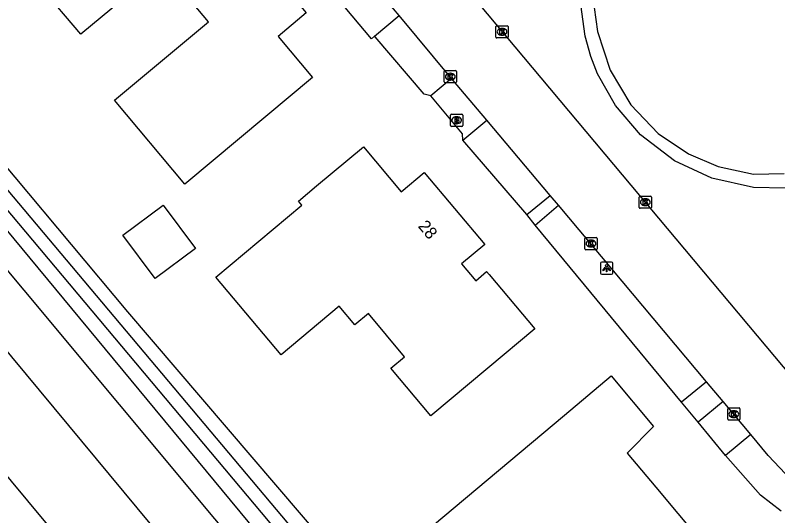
# Model space of a CAD drawing. Extents: x 157321 to 158827, y 386650 to 388532.
# Drawn here: x 158007.1 to 158069.6, y 386912.6 to 386953.6 of the extents above; entities that cross this region are included whole.
import ezdxf

# ---------------------------------------------------------------- set-up
doc = ezdxf.new("R2010")
doc.units = 0
for name, color, linetype in [('IMGEO_Brandkraan', 7, 'Continuous'), ('IMGEO_Groenvoorziening', 7, 'Continuous'), ('IMGEO_Kolk', 7, 'Continuous'), ('IMGEO_Lichtpunt', 7, 'Continuous'), ('IMGEO_Pand', 7, 'Continuous'), ('IMGEO_Pand_nummerreeks', 7, 'Continuous'), ('IMGEO_Rijbaan_lokaal_gesloten', 7, 'Continuous'), ('IMGEO_Voetpad_open', 7, 'Continuous'), ('IMGEO_Waterloop', 7, 'Continuous')]:
    doc.layers.add(name, color=color, linetype=linetype)

msp = doc.modelspace()

# ---------------------------------------------------------------- linework, layer by layer
at = {"layer": 'IMGEO_Brandkraan'}
for p, q in [((158042.816, 386944.616), (158042.816, 386945.468)), ((158042.891, 386945.542), (158043.743, 386945.542)), ((158043.817, 386945.468), (158043.817, 386944.616)), ((158043.304, 386945.322), (158043.329, 386945.322)), ((158043.743, 386944.542), (158042.891, 386944.542)), ((158043.327, 386944.762), (158043.302, 386944.762))]:
    msp.add_line(p, q, dxfattribs=at)
for points in [[(158042.816, 386944.616), (158042.816, 386945.468)], [(158042.891, 386945.542), (158043.743, 386945.542)], [(158043.817, 386945.468), (158043.817, 386944.616)], [(158043.164, 386945.242), (158043.164, 386944.842), (158043.377, 386944.842)], [(158043.395, 386945.242), (158043.164, 386945.242)], [(158043.343, 386945.161), (158043.289, 386945.161), (158043.289, 386945.085)], [(158043.289, 386945.085), (158043.342, 386945.085)], [(158043.351, 386945.009), (158043.289, 386945.009), (158043.289, 386944.928)], [(158043.289, 386944.928), (158043.351, 386944.928)], [(158043.743, 386944.542), (158042.891, 386944.542)]]:
    msp.add_lwpolyline(points, dxfattribs=at)
for centre, radius, start, end in [((158042.893, 386945.466), 0.0765, 91.55205, 178.44795), ((158042.893, 386945.466), 0.0765, 91.55205, 178.44795), ((158043.741, 386945.466), 0.0765, 1.55205, 88.44795), ((158043.741, 386945.466), 0.0765, 1.55205, 88.44795), ((158043.344, 386945.123), 0.0379, 267.82845, 90.93552), ((158043.352, 386944.968), 0.0404, 269.87594, 90.50774), ((158043.383, 386945.093), 0.251, 268.66757, 293.53466), ((158043.399, 386945.097), 0.145, 59.4692, 91.53667), ((158043.424, 386945.144), 0.0922, 285.51372, 58.15012), ((158043.429, 386944.952), 0.105, 301.31148, 78.98903), ((158042.893, 386944.618), 0.0765, 181.55205, 268.44795), ((158042.893, 386944.618), 0.0765, 181.55205, 268.44795), ((158043.741, 386944.618), 0.0765, 271.55205, 358.44795), ((158043.741, 386944.618), 0.0765, 271.55205, 358.44795)]:
    msp.add_arc(centre, radius, start, end, dxfattribs=at)
for centre, major_axis, ratio, start_param, end_param in [((158043.303, 386945.042), (-0.387, 0.002), 0.722429, 4.712389, 7.853982), ((158043.328, 386945.042), (-0.39, 0.002), 0.717154, 1.570796, 4.712389)]:
    msp.add_ellipse(centre, major_axis=major_axis, ratio=ratio, start_param=start_param, end_param=end_param, dxfattribs=at)
at = {"layer": 'IMGEO_Groenvoorziening'}
for points in [[(157915.669, 387039.524), (157916.246, 387034.499), (157917.326, 387029.652), (157918.224, 387026.707), (157925.534, 387014.398), (157933.739, 387003.394), (158036.298, 386879.994), (158040.875, 386875.274), (158045.999, 386870.991), (158051.541, 386867.268), (158057.356, 386864.191), (158059.718, 386863.157), (158065.313, 386860.377), (158069.288, 386859.404), (158071.922, 386859.047), (158074.577, 386858.967), (158077.228, 386859.164), (158080.09, 386859.682), (158109.645, 386869.131), (158107.666, 386875.322)], [(157937.472, 387021.971), (157943.823, 387013.736), (157955.389, 387000), (158000, 386947.022), (158042.278, 386896.814)], [(157938.087, 387014.677), (157950.334, 387000), (158000, 386940.482), (158039.093, 386893.634)], [(157939.879, 387006.192), (157945.025, 387000), (158000, 386933.844), (158041.131, 386884.348)], [(158070.263, 386939.479), (158067.652, 386939.528), (158064.236, 386940.299), (158061.179, 386941.73), (158058.402, 386943.856), (158056.356, 386946.242), (158054.878, 386948.842), (158054.312, 386950.281), (158053.85, 386951.938), (158053.495, 386954.52), (158053.571, 386957.187), (158055, 386966.678)], [(158056.05, 386965.433), (158055.065, 386959.117), (158054.575, 386955.997), (158054.591, 386954.286), (158054.858, 386952.32), (158055.896, 386949.14), (158057.604, 386946.303), (158059.842, 386943.968), (158062.335, 386942.282), (158064.755, 386941.25), (158067.645, 386940.623), (158070.176, 386940.675)], [(158041.197, 386947.04), (158040.654, 386947.173), (158036.643, 386951.87), (158036.592, 386951.93)], [(157997.832, 386951.408), (158016.34, 386929.351), (158048.856, 386891.347), (158052.006, 386888.362), (158054.735, 386886.23), (158061.143, 386882.788), (158063.836, 386881.61), (158066.74, 386880.636), (158072.605, 386879.295), (158075.571, 386878.874), (158081.422, 386878.627), (158087.103, 386878.964), (158090.042, 386879.509), (158092.91, 386880.238), (158101.35, 386883.538), (158104.009, 386884.795), (158111.36, 386888.673), (158097.876, 386904.822), (158091.265, 386912.857)], [(158049.074, 386937.309), (158043.836, 386943.4)], [(158061.764, 386921.937), (158049.754, 386936.46)], [(158065.373, 386917.573), (158063.11, 386920.309)]]:
    msp.add_lwpolyline(points, dxfattribs=at)
at = {"layer": 'IMGEO_Kolk'}
for p, q in [((158046.545, 386951.861), (158046.545, 386952.713)), ((158046.62, 386952.787), (158047.472, 386952.787)), ((158047.033, 386952.567), (158047.058, 386952.567)), ((158047.546, 386952.713), (158047.546, 386951.861)), ((158047.472, 386951.787), (158046.62, 386951.787)), ((158047.056, 386952.007), (158047.031, 386952.007)), ((158042.299, 386948.187), (158042.299, 386949.039)), ((158042.374, 386949.113), (158043.226, 386949.113)), ((158042.787, 386948.893), (158042.812, 386948.893)), ((158043.3, 386949.039), (158043.3, 386948.187)), ((158043.226, 386948.113), (158042.374, 386948.113)), ((158042.81, 386948.333), (158042.785, 386948.333)), ((158058.287, 386937.901), (158058.287, 386938.753)), ((158058.362, 386938.827), (158059.214, 386938.827)), ((158058.775, 386938.607), (158058.8, 386938.607)), ((158059.288, 386938.753), (158059.288, 386937.901)), ((158058.798, 386938.047), (158058.773, 386938.047)), ((158059.214, 386937.827), (158058.362, 386937.827)), ((158053.908, 386935.438), (158054.76, 386935.438)), ((158053.833, 386934.512), (158053.833, 386935.364)), ((158054.321, 386935.218), (158054.346, 386935.218)), ((158054.834, 386935.364), (158054.834, 386934.512)), ((158054.76, 386934.438), (158053.908, 386934.438)), ((158054.344, 386934.658), (158054.319, 386934.658)), ((158065.546, 386920.541), (158065.546, 386921.393)), ((158065.621, 386921.467), (158066.473, 386921.467)), ((158066.034, 386921.247), (158066.059, 386921.247)), ((158066.547, 386921.393), (158066.547, 386920.541)), ((158066.473, 386920.467), (158065.621, 386920.467)), ((158066.057, 386920.687), (158066.032, 386920.687))]:
    msp.add_line(p, q, dxfattribs=at)
for points in [[(158046.545, 386951.861), (158046.545, 386952.713)], [(158046.62, 386952.787), (158047.472, 386952.787)], [(158046.866, 386952.487), (158046.989, 386952.487), (158046.989, 386952.336), (158047.119, 386952.487), (158047.283, 386952.487), (158047.137, 386952.336), (158047.29, 386952.087), (158047.138, 386952.087), (158047.053, 386952.251), (158046.989, 386952.184), (158046.989, 386952.087), (158046.866, 386952.087), (158046.866, 386952.487)], [(158047.546, 386952.713), (158047.546, 386951.861)], [(158047.472, 386951.787), (158046.62, 386951.787)], [(158042.299, 386948.187), (158042.299, 386949.039)], [(158042.374, 386949.113), (158043.226, 386949.113)], [(158042.62, 386948.813), (158042.743, 386948.813), (158042.743, 386948.662), (158042.873, 386948.813), (158043.037, 386948.813), (158042.891, 386948.662), (158043.044, 386948.413), (158042.892, 386948.413), (158042.807, 386948.577), (158042.743, 386948.51), (158042.743, 386948.413), (158042.62, 386948.413), (158042.62, 386948.813)], [(158043.3, 386949.039), (158043.3, 386948.187)], [(158043.226, 386948.113), (158042.374, 386948.113)], [(158058.287, 386937.901), (158058.287, 386938.753)], [(158058.362, 386938.827), (158059.214, 386938.827)], [(158058.608, 386938.527), (158058.731, 386938.527), (158058.731, 386938.376), (158058.861, 386938.527), (158059.025, 386938.527), (158058.879, 386938.376), (158059.032, 386938.127), (158058.88, 386938.127), (158058.795, 386938.291), (158058.731, 386938.224), (158058.731, 386938.127), (158058.608, 386938.127), (158058.608, 386938.527)], [(158059.288, 386938.753), (158059.288, 386937.901)], [(158059.214, 386937.827), (158058.362, 386937.827)], [(158053.908, 386935.438), (158054.76, 386935.438)], [(158053.833, 386934.512), (158053.833, 386935.364)], [(158054.154, 386935.138), (158054.277, 386935.138), (158054.277, 386934.987), (158054.407, 386935.138), (158054.571, 386935.138), (158054.425, 386934.987), (158054.578, 386934.738), (158054.426, 386934.738), (158054.341, 386934.902), (158054.277, 386934.835), (158054.277, 386934.738), (158054.154, 386934.738), (158054.154, 386935.138)], [(158054.834, 386935.364), (158054.834, 386934.512)], [(158054.76, 386934.438), (158053.908, 386934.438)], [(158065.546, 386920.541), (158065.546, 386921.393)], [(158065.621, 386921.467), (158066.473, 386921.467)], [(158065.867, 386921.167), (158065.99, 386921.167), (158065.99, 386921.016), (158066.12, 386921.167), (158066.284, 386921.167), (158066.138, 386921.016), (158066.291, 386920.767), (158066.139, 386920.767), (158066.054, 386920.931), (158065.99, 386920.864), (158065.99, 386920.767), (158065.867, 386920.767), (158065.867, 386921.167)], [(158066.547, 386921.393), (158066.547, 386920.541)], [(158066.473, 386920.467), (158065.621, 386920.467)]]:
    msp.add_lwpolyline(points, dxfattribs=at)
for centre, start, end in [((158046.622, 386952.711), 91.55205, 178.44795), ((158046.622, 386952.711), 91.55205, 178.44795), ((158047.47, 386952.711), 1.55205, 88.44795), ((158047.47, 386952.711), 1.55205, 88.44795), ((158046.622, 386951.863), 181.55205, 268.44795), ((158046.622, 386951.863), 181.55205, 268.44795), ((158047.47, 386951.863), 271.55205, 358.44795), ((158047.47, 386951.863), 271.55205, 358.44795), ((158042.376, 386949.037), 91.55205, 178.44795), ((158042.376, 386949.037), 91.55205, 178.44795), ((158043.224, 386949.037), 1.55205, 88.44795), ((158043.224, 386949.037), 1.55205, 88.44795), ((158042.376, 386948.189), 181.55205, 268.44795), ((158042.376, 386948.189), 181.55205, 268.44795), ((158043.224, 386948.189), 271.55205, 358.44795), ((158043.224, 386948.189), 271.55205, 358.44795), ((158058.364, 386938.751), 91.55205, 178.44795), ((158058.364, 386938.751), 91.55205, 178.44795), ((158059.212, 386938.751), 1.55205, 88.44795), ((158059.212, 386938.751), 1.55205, 88.44795), ((158058.364, 386937.903), 181.55205, 268.44795), ((158058.364, 386937.903), 181.55205, 268.44795), ((158059.212, 386937.903), 271.55205, 358.44795), ((158059.212, 386937.903), 271.55205, 358.44795), ((158053.91, 386935.362), 91.55205, 178.44795), ((158053.91, 386935.362), 91.55205, 178.44795), ((158054.758, 386935.362), 1.55205, 88.44795), ((158054.758, 386935.362), 1.55205, 88.44795), ((158053.91, 386934.514), 181.55205, 268.44795), ((158053.91, 386934.514), 181.55205, 268.44795), ((158054.758, 386934.514), 271.55205, 358.44795), ((158054.758, 386934.514), 271.55205, 358.44795), ((158065.623, 386921.391), 91.55205, 178.44795), ((158065.623, 386921.391), 91.55205, 178.44795), ((158066.471, 386921.391), 1.55205, 88.44795), ((158066.471, 386921.391), 1.55205, 88.44795), ((158065.623, 386920.543), 181.55205, 268.44795), ((158065.623, 386920.543), 181.55205, 268.44795), ((158066.471, 386920.543), 271.55205, 358.44795), ((158066.471, 386920.543), 271.55205, 358.44795)]:
    msp.add_arc(centre, 0.0765, start, end, dxfattribs=at)
for centre, major_axis, ratio, start_param, end_param in [((158047.032, 386952.287), (-0.387, 0.002), 0.722429, 4.712389, 7.853982), ((158047.057, 386952.287), (-0.39, 0.002), 0.717154, 1.570796, 4.712389), ((158042.786, 386948.613), (-0.387, 0.002), 0.722429, 4.712389, 7.853982), ((158042.811, 386948.613), (-0.39, 0.002), 0.717154, 1.570796, 4.712389), ((158058.774, 386938.327), (-0.387, 0.002), 0.722429, 4.712389, 7.853982), ((158058.799, 386938.327), (-0.39, 0.002), 0.717154, 1.570796, 4.712389), ((158054.32, 386934.938), (-0.387, 0.002), 0.722429, 4.712389, 7.853982), ((158054.345, 386934.938), (-0.39, 0.002), 0.717154, 1.570796, 4.712389), ((158066.033, 386920.967), (-0.387, 0.002), 0.722429, 4.712389, 7.853982), ((158066.058, 386920.967), (-0.39, 0.002), 0.717154, 1.570796, 4.712389)]:
    msp.add_ellipse(centre, major_axis=major_axis, ratio=ratio, start_param=start_param, end_param=end_param, dxfattribs=at)
at = {"layer": 'IMGEO_Lichtpunt'}
for p, q in [((158055.118, 386933.328), (158055.118, 386932.521)), ((158055.118, 386933.328), (158055.118, 386932.521)), ((158056.02, 386933.423), (158055.212, 386933.423)), ((158056.02, 386933.423), (158055.212, 386933.423)), ((158056.114, 386932.521), (158056.114, 386933.328)), ((158056.114, 386932.521), (158056.114, 386933.328)), ((158055.212, 386932.427), (158056.02, 386932.427)), ((158055.212, 386932.427), (158056.02, 386932.427))]:
    msp.add_line(p, q, dxfattribs=at)
for points in [[(158055.492, 386932.992), (158055.531, 386932.964), (158055.343, 386932.702), (158055.305, 386932.729), (158055.492, 386932.992)], [(158055.594, 386932.944), (158055.641, 386932.944), (158055.641, 386932.622), (158055.594, 386932.622), (158055.594, 386932.944)], [(158055.704, 386932.964), (158055.742, 386932.991), (158055.929, 386932.729), (158055.89, 386932.701), (158055.704, 386932.964)]]:
    msp.add_lwpolyline(points, dxfattribs=at)
msp.add_circle((158055.617, 386933.126), 0.0994, dxfattribs=at)
for centre, start, end in [((158055.212, 386933.328), 90, 180), ((158055.212, 386933.328), 90, 180), ((158056.02, 386933.328), 0, 90), ((158056.02, 386933.328), 0, 90), ((158055.212, 386932.521), 180, 270), ((158055.212, 386932.521), 180, 270), ((158056.02, 386932.521), 270, 0), ((158056.02, 386932.521), 270, 360)]:
    msp.add_arc(centre, 0.0946, start, end, dxfattribs=at)
at = {"layer": 'IMGEO_Pand'}
for points in [[(158016.504, 386962.101), (158020.335, 386965.313), (158024.467, 386960.406), (158025.064, 386960.909), (158028.925, 386956.316), (158028.489, 386955.95), (158029.563, 386954.671), (158029.999, 386955.037), (158030.996, 386953.85), (158028.685, 386951.9), (158031.502, 386948.56), (158027.669, 386945.35), (158021.051, 386939.806), (158015.277, 386946.677), (158022.978, 386953.106), (158019.17, 386957.649), (158012.501, 386952.091), (158009.217, 386955.992), (158016.504, 386962.101)], [(158030.62, 386938.091), (158030.345, 386938.422), (158031.841, 386939.67), (158035.681, 386942.871), (158038.762, 386939.177), (158040.667, 386940.769), (158045.62, 386934.872), (158043.729, 386933.285), (158044.893, 386931.899), (158045.781, 386932.644), (158045.98, 386932.407), (158049.72, 386927.948), (158045.89, 386924.735), (158041.213, 386920.812), (158037.931, 386924.734), (158039.043, 386925.664), (158036.084, 386929.2), (158034.972, 386928.269), (158033.689, 386929.803), (158028.932, 386925.823), (158023.577, 386932.198), (158030.62, 386938.091)], [(158021.921, 386934.532), (158018.608, 386932.067), (158015.96, 386935.626), (158019.273, 386938.09), (158021.921, 386934.532)], [(158052.153, 386920.889), (158055.975, 386924.102), (158059.456, 386919.959), (158057.305, 386917.776), (158059.642, 386914.984), (158064.926, 386908.671), (158067.29, 386910.624), (158067.454, 386910.449), (158063.627, 386907.233), (158054.184, 386899.318), (158048.988, 386894.963), (158046.168, 386898.328), (158049.98, 386903.406), (158041.347, 386911.802), (158052.153, 386920.889)]]:
    msp.add_lwpolyline(points, dxfattribs=at)
at = {"layer": 'IMGEO_Rijbaan_lokaal_gesloten'}
for points in [[(158041.42, 386959.024), (158073.076, 386921.282)], [(158038.597, 386953.625), (158035.357, 386957.488)], [(158042.903, 386948.477), (158038.597, 386953.625)], [(158045.801, 386945.052), (158042.903, 386948.477)], [(158050.997, 386938.872), (158045.801, 386945.052)], [(158051.663, 386938.08), (158050.997, 386938.872)], [(158063.817, 386923.608), (158051.663, 386938.08)], [(158065.16, 386922.009), (158063.817, 386923.608)], [(158067.446, 386919.287), (158065.16, 386922.009)], [(158070.286, 386916.061), (158068.865, 386917.568), (158067.446, 386919.287)]]:
    msp.add_lwpolyline(points, dxfattribs=at)
at = {"layer": 'IMGEO_Voetpad_open'}
for points in [[(158036.592, 386951.93), (158036.351, 386951.727), (158033.168, 386955.508), (158033.423, 386955.739)], [(158036.592, 386951.93), (158038.597, 386953.625)], [(158042.903, 386948.477), (158041.197, 386947.04)], [(158043.836, 386943.4), (158043.806, 386943.933), (158041.197, 386947.04)], [(158043.836, 386943.4), (158045.801, 386945.052)], [(158049.074, 386937.309), (158050.997, 386938.872)], [(158049.754, 386936.46), (158051.663, 386938.08)], [(158049.754, 386936.46), (158049.074, 386937.309)], [(158063.817, 386923.608), (158061.764, 386921.937)], [(158063.11, 386920.309), (158061.764, 386921.937)], [(158065.16, 386922.009), (158063.11, 386920.309)], [(158067.446, 386919.287), (158065.373, 386917.573)], [(158069.919, 386913.022), (158068.222, 386914.313), (158065.373, 386917.573)]]:
    msp.add_lwpolyline(points, dxfattribs=at)
at = {"layer": 'IMGEO_Waterloop'}
for points in [[(158095.701, 386911.342), (158111.4, 386892.389), (158113.022, 386890.458), (158113.833, 386888.489), (158112.829, 386886.635), (158101.398, 386881.267), (158093.944, 386878.448), (158091.801, 386878.081), (158083.999, 386876.845), (158071.525, 386877.849), (158063.26, 386880.012), (158059.862, 386881.556), (158050.67, 386886.616), (158047.349, 386889.435), (158044.337, 386892.64), (157951.031, 387003.711), (157941.028, 387015.529), (157936.703, 387021.226), (157932.995, 387028.081), (157930.292, 387037.813), (157929.635, 387046.889), (157929.79, 387051.06), (157930.408, 387058.32), (157934.617, 387071.335)], [(157932.204, 387070.08), (157929.693, 387061.429), (157928.612, 387057.181), (157927.955, 387046.676), (157928.805, 387037.253), (157931.586, 387027.907), (157935.448, 387020.801), (157938.923, 387016.244), (157998.707, 386945.337), (158035.782, 386900.577), (158043.159, 386891.424), (158050.149, 386885.438), (158062.314, 386879.181), (158071.815, 386876.632), (158084.328, 386875.937), (158092.747, 386877.096), (158100.007, 386879.259), (158111.632, 386884.434), (158113.447, 386885.476), (158114.335, 386886.828), (158115.146, 386888.643), (158114.722, 386890.304), (158096.532, 386911.95), (158095.701, 386911.342)]]:
    msp.add_lwpolyline(points, dxfattribs=at)

# ---------------------------------------------------------------- texts
at = {"layer": 'IMGEO_Pand_nummerreeks'}
msp.add_text('28', height=1, rotation=310.02662, dxfattribs=at).set_placement((158040.103, 386936.341))

doc.saveas('drawing.dxf')
